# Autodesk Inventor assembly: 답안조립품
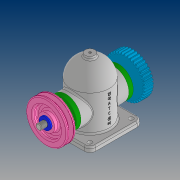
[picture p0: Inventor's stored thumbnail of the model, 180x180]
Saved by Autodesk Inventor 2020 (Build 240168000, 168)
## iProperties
Created: 2021-08
Part Number: 답안조립품
Document SubType Name: Assembly
Designer: PC312-
Author: PC312-
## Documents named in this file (13)
- C:\Users\PC312-\Desktop\710809V1005\답안조립품.iam
- C:\Users\PC312-\Desktop\710809V1005\본체.ipt
- C:\Users\PC312-\Desktop\710809V1005\축.ipt
- C:\Users\PC312-\Desktop\710809V1005\베어링 6203.ipt
- C:\Users\PC312-\Desktop\710809V1005\부시.ipt
- C:\Users\PC312-\Desktop\710809V1005\커버.ipt
- C:\Users\PC312-\Desktop\710809V1005\오일 실 26 38 8.ipt
- C:\Users\PC312-\Desktop\710809V1005\볼트 M4.ipt
- C:\Users\PC312-\Desktop\710809V1005\키 5x5x12.ipt
- C:\Users\PC312-\Desktop\710809V1005\V-벨트풀리.ipt
- V-벨트풀리.ipt
- C:\Users\PC312-\Desktop\710809V1005\스퍼기어.ipt
- C:\Users\PC312-\Desktop\710809V1005\와셔 12x24.ipt
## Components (1 placed, 1 different names)
1. V-벨트풀리:1
